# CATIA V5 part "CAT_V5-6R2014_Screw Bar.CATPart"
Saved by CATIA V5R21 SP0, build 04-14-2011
Part number: Screw Bar
Bounding box of the stored display mesh (mm): x -3 to 3, y -52 to 52, z -2.853 to 2.853
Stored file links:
  D:\CATIA V5R21 E-RESOURCES\CATIA-V5R21\catia-v5r21-prt\c16-catia-v5r20-prt\c16-catia-v5r21-tut01\CAT_V5R21_Screw Bar.CATPart
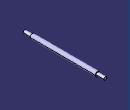
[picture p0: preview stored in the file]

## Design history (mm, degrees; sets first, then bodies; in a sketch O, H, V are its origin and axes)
Body1 (main body)
  Sketch1 on zx-plane, origin (0, 0, 0), H (-1, 0, 0), V (0, 0, 1)
    circle A1 centre (0, 0) radius 2
    radius A1 = 2
  Sketch2 on zx-plane, origin (0, 0, 0), H (-1, 0, 0), V (0, 0, 1)
    circle A1 centre (0, 0) radius 3
    radius A1 = 3
  Pad1: profile Sketch1, direction (0, 1, 0), length 52, mirrored extent
  Pad2: profile Sketch2, direction (0, 1, 0), length 42, mirrored extent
